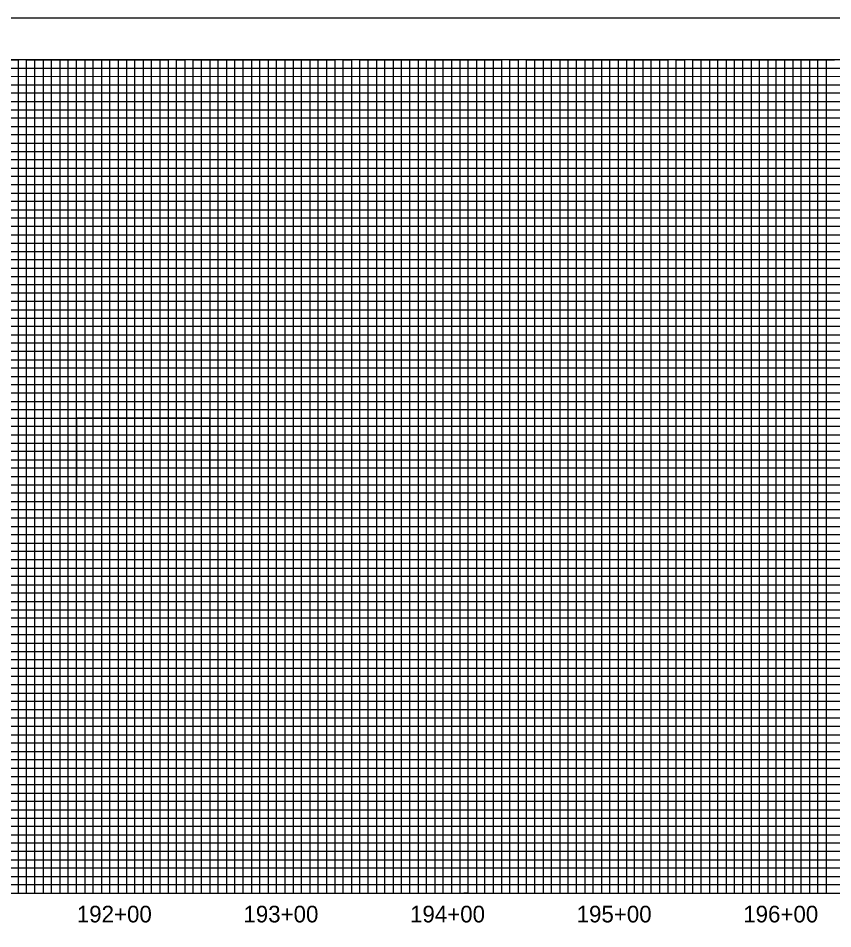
# Model space of a CAD drawing. Extents: x 505602 to 507286, y 483109 to 484209.
# Drawn here: x 506359 to 506848, y 483662 to 484209 of the extents above; entities that cross this region are included whole.
import ezdxf

# ---------------------------------------------------------------- set-up
doc = ezdxf.new("R2010")
doc.units = 0
for name, color, linetype in [('Exist Vertical Profile Vertical Axis Label', 7, 'Continuous'), ('Prop Grid Mask', 7, 'Continuous'), ('Sheet Layout Profile Border Port 1', 7, 'Continuous'), ('Sheet Plot Border Outside CELL', 7, 'Continuous'), ('Sheet Profile CELL', 7, 'Continuous'), ('Sheet Profile Grid Major CELL', 7, 'Continuous'), ('Sheet Profile Grid Middle CELL', 7, 'Continuous'), ('Sheet Profile Grid Minor CELL', 7, 'Continuous')]:
    doc.layers.add(name, color=color, linetype=linetype)

msp = doc.modelspace()

# ---------------------------------------------------------------- linework, layer by layer
at = {"layer": 'Prop Grid Mask'}
msp.add_lwpolyline([(506394.08, 483928.71), (506474.08, 483928.71), (506474.08, 483968.71), (506394.08, 483968.71)], close=True, dxfattribs=at)
at = {"layer": 'Sheet Layout Profile Border Port 1'}
msp.add_lwpolyline([(505819.08, 484183.71), (505819.08, 483683.71), (507219.08, 483683.71), (507219.08, 484022.66), (507069.03, 484022.66), (507069.03, 484183.71)], close=True, dxfattribs=at)
at = {"layer": 'Sheet Plot Border Outside CELL'}
msp.add_lwpolyline([(505602.08, 483108.71), (507286.08, 483108.71), (507286.08, 484208.71), (505602.08, 484208.71)], close=True, dxfattribs=at)
at = {"layer": 'Sheet Profile CELL'}
msp.add_line((505769.08, 483683.71), (507269.08, 483683.71), dxfattribs=at)
msp.add_lwpolyline([(507269.08, 484183.71), (505769.08, 484183.71), (505769.08, 483133.71), (507269.08, 483133.71)], close=True, dxfattribs=at)
at = {"layer": 'Sheet Profile Grid Major CELL'}
for points in [[(506319.08, 483683.71), (506369.08, 483683.71), (506369.08, 484183.71), (506419.08, 484183.71), (506419.08, 483683.71), (506469.08, 483683.71), (506469.08, 484183.71), (506519.08, 484183.71), (506519.08, 483683.71), (506569.08, 483683.71), (506569.08, 484183.71), (506619.08, 484183.71), (506619.08, 483683.71), (506669.08, 483683.71), (506669.08, 484183.71), (506719.08, 484183.71), (506719.08, 483683.71), (506769.08, 483683.71), (506769.08, 484183.71), (506819.08, 484183.71), (506819.08, 483683.71), (506869.08, 483683.71)], [(505769.08, 484133.71), (507069.08, 484133.71)], [(507069.08, 484083.71), (505769.08, 484083.71), (505769.08, 484033.71), (507069.08, 484033.71)], [(507269.08, 483983.71), (505769.08, 483983.71), (505769.08, 483933.71), (507269.08, 483933.71)], [(507269.08, 483883.71), (505769.08, 483883.71), (505769.08, 483833.71), (507269.08, 483833.71)], [(507269.08, 483783.71), (505769.08, 483783.71), (505769.08, 483783.71), (505769.08, 483733.71), (507269.08, 483733.71)]]:
    msp.add_lwpolyline(points, dxfattribs=at)
at = {"layer": 'Sheet Profile Grid Middle CELL'}
msp.add_line((505769.08, 484158.71), (507069.03, 484158.71), dxfattribs=at)
for points in [[(506344.08, 483683.71), (506394.08, 483683.71), (506394.08, 483683.71), (506394.08, 484183.71), (506444.08, 484183.71), (506444.08, 483683.71), (506494.08, 483683.71), (506494.08, 484183.71), (506544.08, 484183.71), (506544.08, 483683.71), (506594.08, 483683.71), (506594.08, 484183.71), (506644.08, 484183.71), (506644.08, 483683.71), (506694.08, 483683.71), (506694.08, 484183.71), (506744.08, 484183.71), (506744.08, 483683.71), (506794.08, 483683.71), (506794.08, 484183.71), (506844.08, 484183.71), (506844.08, 483683.71), (506894.08, 483683.71)], [(507069.08, 484108.71), (505769.08, 484108.71), (505769.08, 484058.71), (507069.08, 484058.71)], [(507269.08, 484008.71), (505769.08, 484008.71), (505769.08, 483958.71), (507094.08, 483958.71)], [(507269.08, 483908.71), (505769.08, 483908.71), (505769.08, 483858.71), (507269.08, 483858.71)], [(507269.08, 483808.71), (505769.08, 483808.71), (505769.08, 483758.71), (507269.08, 483758.71)], [(507269.08, 483708.71), (505769.08, 483708.71)]]:
    msp.add_lwpolyline(points, dxfattribs=at)
at = {"layer": 'Sheet Profile Grid Minor CELL'}
for p, q in [((505819.08, 484178.71), (507069.08, 484178.71)), ((507069.08, 484173.71), (505819.08, 484173.36)), ((505819.08, 484168.71), (507069.08, 484168.71)), ((507069.03, 484048.71), (505819.08, 484048.71)), ((507069.08, 484043.71), (505819.08, 484043.71)), ((507069.08, 484038.71), (505819.08, 484038.71)), ((505819.08, 484028.71), (507069.08, 484028.71)), ((507069.08, 484023.71), (505819.08, 484023.71)), ((505819.08, 484018.71), (507219.08, 484018.71)), ((507219.08, 483998.71), (505819.08, 483998.71)), ((505819.08, 483993.71), (507219.08, 483993.71)), ((507219.08, 483973.71), (505819.08, 483973.71)), ((505819.08, 483968.71), (507219.08, 483968.71)), ((507219.08, 483948.71), (505819.08, 483948.71)), ((505819.08, 483943.71), (507219.08, 483943.71)), ((507219.08, 483938.71), (505819.08, 483938.71)), ((505819.08, 483928.71), (507219.08, 483928.71)), ((507219.08, 483923.71), (505819.08, 483923.71)), ((505819.08, 483918.71), (507219.08, 483918.71)), ((507219.08, 483913.71), (505819.08, 483913.71)), ((505819.08, 483903.71), (507219.08, 483903.71)), ((507219.08, 483898.71), (505819.08, 483898.71)), ((505819.08, 483893.71), (507219.08, 483893.71)), ((507219.08, 483888.71), (505819.08, 483888.71)), ((505819.08, 483878.71), (507219.08, 483878.71)), ((507219.08, 483873.71), (505819.08, 483873.71)), ((505819.08, 483868.71), (507219.08, 483868.71)), ((507219.08, 483863.71), (505819.08, 483863.71)), ((505819.08, 483853.71), (507219.08, 483853.71)), ((507219.08, 483848.71), (505819.08, 483848.71)), ((505819.08, 483843.71), (507219.08, 483843.71)), ((507219.08, 483838.71), (505819.08, 483838.71)), ((505819.08, 483828.71), (507219.08, 483828.71)), ((507219.08, 483823.71), (505819.08, 483823.71)), ((505819.08, 483818.71), (507219.08, 483818.71)), ((507219.08, 483813.71), (505819.08, 483813.71)), ((505819.08, 483803.71), (507219.08, 483803.71)), ((507219.08, 483798.71), (505819.08, 483798.71)), ((507219.08, 483793.71), (505819.08, 483793.71)), ((507219.08, 483788.71), (505819.08, 483788.71)), ((505819.08, 483778.71), (507219.08, 483778.71)), ((507219.08, 483773.71), (505819.08, 483773.71)), ((505819.08, 483768.71), (507219.08, 483768.71)), ((507219.08, 483763.71), (505819.08, 483763.71)), ((505819.08, 483753.71), (507219.08, 483753.71)), ((507219.08, 483748.71), (505819.08, 483748.71)), ((505819.08, 483743.71), (507219.08, 483743.71)), ((507219.08, 483738.71), (505819.08, 483738.71)), ((505819.08, 483728.71), (507219.08, 483728.71)), ((507219.08, 483723.71), (505819.08, 483723.71)), ((505819.08, 483718.71), (507219.08, 483718.71)), ((507219.08, 483713.71), (505819.08, 483713.71)), ((505819.08, 483703.71), (507219.08, 483703.71)), ((507219.08, 483698.71), (505819.08, 483698.71)), ((505819.08, 483693.71), (507219.08, 483693.71))]:
    msp.add_line(p, q, dxfattribs=at)
for points in [[(506354.08, 484183.71), (506359.08, 484183.71), (506359.08, 483683.71), (506364.08, 483683.71), (506364.08, 484183.71), (506374.08, 484183.71), (506374.08, 483683.71), (506379.08, 483683.71), (506379.08, 484183.71), (506384.08, 484183.71), (506384.08, 483683.71), (506389.08, 483683.71), (506389.08, 484183.71), (506399.08, 484183.71), (506399.08, 483683.71), (506404.08, 483683.71), (506404.08, 484183.71), (506409.08, 484183.71), (506409.08, 483683.71), (506414.08, 483683.71), (506414.08, 484183.71), (506424.08, 484183.71), (506424.08, 483683.71), (506429.08, 483683.71), (506429.08, 484183.71), (506434.08, 484183.71), (506434.08, 483683.71), (506439.08, 483683.71), (506439.08, 484183.71), (506449.08, 484183.71), (506449.08, 483683.71), (506454.08, 483683.71), (506454.08, 484183.71), (506459.08, 484183.71), (506459.08, 483683.71), (506464.08, 483683.71), (506464.08, 484183.71), (506474.08, 484183.71), (506474.08, 483683.71), (506474.08, 483683.71), (506479.08, 483683.71), (506479.08, 484183.71), (506484.08, 484183.71), (506484.08, 483683.71), (506489.08, 483683.71), (506489.08, 484183.71), (506499.08, 484183.71), (506499.08, 483683.71), (506504.08, 483683.71), (506504.08, 484183.71), (506509.08, 484183.71), (506509.08, 483683.71), (506514.08, 483683.71), (506514.08, 484183.71), (506524.08, 484183.71), (506524.08, 483683.71), (506529.08, 483683.71), (506529.08, 484183.71), (506534.08, 484183.71), (506534.08, 483683.71), (506539.08, 483683.71), (506539.08, 484183.71), (506549.08, 484183.71), (506549.08, 483683.71), (506554.08, 483683.71), (506554.08, 484183.71), (506559.08, 484183.71), (506559.08, 483683.71), (506564.08, 483683.71), (506564.08, 484183.71), (506574.08, 484183.71), (506574.08, 483683.71), (506579.08, 483683.71), (506579.08, 484183.71), (506584.08, 484183.71), (506584.08, 483683.71), (506589.08, 483683.71), (506589.08, 484183.71), (506599.08, 484183.71), (506599.08, 483683.71), (506604.08, 483683.71), (506604.08, 484183.71), (506609.08, 484183.71), (506609.08, 483683.71), (506614.08, 483683.71), (506614.08, 484183.71), (506624.08, 484183.71), (506624.08, 483683.71), (506628.78, 483684.26), (506629.08, 483683.71), (506629.08, 484183.71), (506634.08, 484183.71), (506634.08, 483683.71), (506639.08, 483683.71), (506639.08, 484183.71), (506649.08, 484183.71), (506649.08, 483683.71), (506654.08, 483683.71)], [(506654.08, 483683.71), (506654.08, 484183.71), (506659.08, 484183.71), (506659.08, 483683.71), (506664.08, 483683.71), (506664.08, 484183.71), (506674.08, 484183.71), (506674.08, 483683.71), (506679.08, 483683.71), (506679.08, 484183.71), (506684.08, 484183.71), (506684.08, 483683.71), (506689.08, 483683.71), (506689.08, 484183.71), (506699.08, 484183.71), (506699.08, 483683.71), (506704.08, 483683.71), (506704.08, 484183.71), (506709.08, 484183.71), (506709.08, 483683.71), (506714.08, 483683.71), (506714.08, 484183.71), (506724.08, 484183.71), (506724.08, 483683.71), (506729.08, 483683.71), (506729.08, 484183.71), (506734.08, 484183.71), (506734.08, 483683.71), (506739.08, 483683.71), (506739.08, 484183.71), (506749.08, 484183.71), (506749.08, 483683.71), (506754.08, 483683.71), (506754.08, 484183.71), (506759.08, 484183.71), (506759.08, 483683.71), (506764.08, 483683.71), (506764.08, 484183.71), (506774.08, 484183.71), (506774.08, 483683.71), (506779.08, 483683.71), (506779.08, 484183.71), (506784.08, 484183.71), (506784.08, 483683.71), (506789.08, 483683.71), (506789.08, 484183.71), (506799.08, 484183.71), (506799.08, 483683.71), (506804.08, 483683.71), (506804.08, 484183.71), (506809.08, 484183.71), (506809.08, 483683.71), (506814.08, 483683.71), (506814.08, 484183.71), (506824.08, 484183.71), (506824.08, 483683.71), (506829.08, 483683.71), (506829.08, 484183.71), (506834.08, 484183.71), (506834.08, 483683.71), (506839.08, 483683.71), (506839.08, 484183.71), (506849.08, 484183.71)], [(507069.08, 484163.71), (505819.08, 484163.71), (505819.08, 484153.71), (507069.08, 484153.71)], [(507069.03, 484148.71), (505819.08, 484148.71), (505819.08, 484143.71), (507069.08, 484143.71)], [(507069.08, 484138.71), (505819.08, 484138.71), (505819.08, 484128.71), (507069.08, 484128.71)], [(507069.08, 484123.71), (505819.08, 484123.71), (505819.08, 484118.71), (507069.08, 484118.71)], [(507069.08, 484113.71), (505819.08, 484113.71), (505819.08, 484103.71), (507069.08, 484103.71)], [(507069.08, 484098.71), (505819.08, 484098.71), (505819.08, 484093.71), (507069.08, 484093.71)], [(507069.08, 484088.71), (505819.08, 484088.71), (505819.08, 484078.71), (507069.08, 484078.71)], [(507069.08, 484073.61), (505819.18, 484073.61), (505819.18, 484068.71), (507069.08, 484068.71)], [(507069.08, 484063.71), (505819.08, 484063.71), (505819.08, 484053.71), (507069.08, 484053.71)], [(507219.08, 484013.71), (505819.08, 484013.71), (505819.08, 484003.71), (507219.08, 484003.71)], [(507219.08, 483988.71), (505819.08, 483988.71), (505819.08, 483978.71), (507219.08, 483978.71)], [(507219.08, 483963.71), (505819.08, 483963.71), (505819.08, 483953.71), (507219.08, 483953.71)], [(507219.08, 483688.71), (505819.08, 483688.71)]]:
    msp.add_lwpolyline(points, dxfattribs=at)

# ---------------------------------------------------------------- texts
at = {"layer": 'Exist Vertical Profile Vertical Axis Label'}
for s, p in [('192+00', (506394.26, 483666.21)), ('193+00', (506494.26, 483666.21)), ('194+00', (506594.26, 483666.21)), ('195+00', (506694.26, 483666.21)), ('196+00', (506794.26, 483666.21))]:
    msp.add_text(s, height=10, dxfattribs=at).set_placement(p)

doc.saveas('drawing.dxf')
